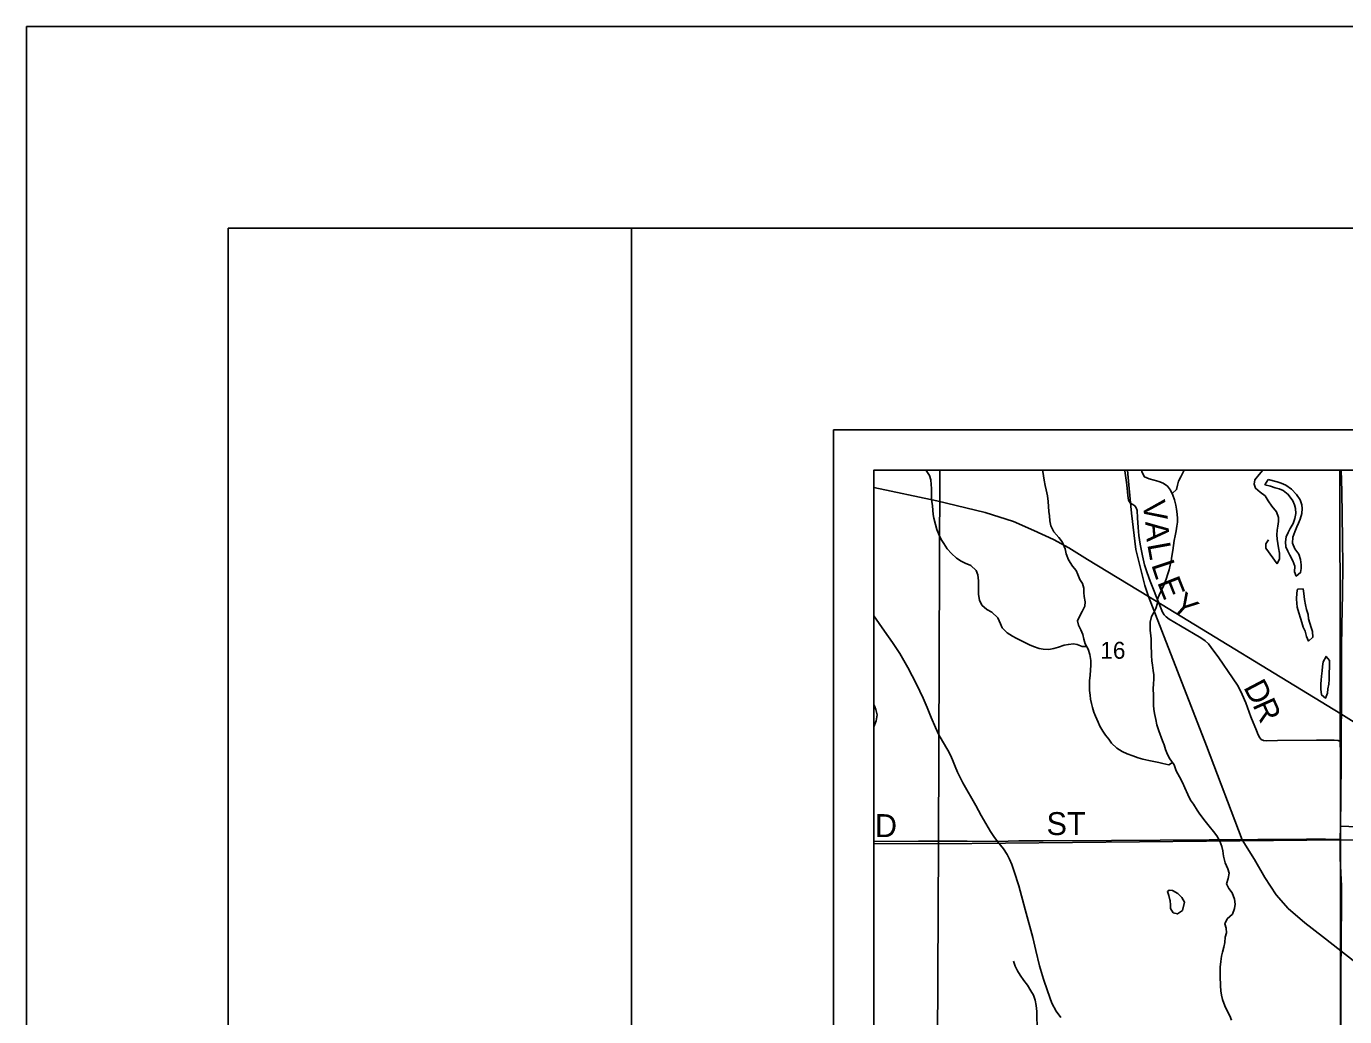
# Model space of a CAD drawing. Extents: x 0 to 34, y 0 to 22.
# Drawn here: x 0 to 3.267, y 19.546 to 22 of the extents above; entities that cross this region are included whole.
import ezdxf

# ---------------------------------------------------------------- set-up
doc = ezdxf.new("R2010")
doc.units = 0
for name, color, linetype in [('Default', 7, 'Continuous'), ('SH_Border', 7, 'Continuous'), ('SH_Cut_Line', 7, 'Continuous'), ('SH_Data', 7, 'Continuous')]:
    doc.layers.add(name, color=color, linetype=linetype)

msp = doc.modelspace()

# ---------------------------------------------------------------- linework, layer by layer
at = {"layer": 'Default'}
msp.add_line((3.2569, 20.0177), (3.2565, 19.9852), dxfattribs=at)
for points in [[(2.264, 20.9), (2.1, 20.9), (2.1, 19.9754), (2.2603, 19.9741)], [(3.255, 20.9), (2.264, 20.9), (2.2603, 19.9741), (3.2572, 19.9844)], [(4.26, 20.9), (3.255, 20.9), (3.2572, 19.9844), (4.2696, 19.9768)], [(2.1, 19.9754), (2.1, 18.9883), (2.2553, 18.9881), (2.2603, 19.9741)], [(2.2603, 19.9741), (3.2572, 19.9844), (3.2565, 18.9852), (2.2553, 18.9881)], [(4.2696, 19.9768), (4.2649, 18.9814), (3.2565, 18.9852), (3.2572, 19.9844)]]:
    msp.add_lwpolyline(points, close=True, dxfattribs=at)
for points in [[(6.2315, 20.9), (2.1, 20.9), (2.1, 17.0156)], [(2.6277, 20.4635), (2.6166, 20.463), (2.6044, 20.4685), (2.5949, 20.4695), (2.5824, 20.4686), (2.5718, 20.4662), (2.5579, 20.4618), (2.5465, 20.4582), (2.5344, 20.4561), (2.5204, 20.4563), (2.5097, 20.4581), (2.496, 20.4636), (2.4865, 20.4672), (2.4766, 20.472), (2.4628, 20.4791), (2.4533, 20.4842), (2.4437, 20.489), (2.4307, 20.4972), (2.418, 20.5096), (2.4141, 20.5198), (2.4074, 20.5341), (2.3932, 20.548), (2.3806, 20.555), (2.3683, 20.5658), (2.3621, 20.5779), (2.36, 20.5923), (2.3595, 20.6258), (2.3582, 20.6405), (2.3542, 20.6515), (2.3404, 20.6639), (2.327, 20.6694), (2.3171, 20.6745), (2.3052, 20.682), (2.2926, 20.6936), (2.2822, 20.7056), (2.2736, 20.7184), (2.2674, 20.7282), (2.2624, 20.7391), (2.2568, 20.7535), (2.2533, 20.7652), (2.2493, 20.7811), (2.2476, 20.7906), (2.2463, 20.8012), (2.2454, 20.8122), (2.2441, 20.8228), (2.2436, 20.8331), (2.2431, 20.8437), (2.2433, 20.8551), (2.2428, 20.8646), (2.2419, 20.8764), (2.2387, 20.8869), (2.2313, 20.8971), (2.2293, 20.9)], [(2.8403, 20.1758), (2.8315, 20.1701), (2.8167, 20.1733), (2.8064, 20.1758), (2.7939, 20.1787), (2.7817, 20.1808), (2.7669, 20.184), (2.7551, 20.1876), (2.7421, 20.192), (2.728, 20.1971), (2.7154, 20.2027), (2.7028, 20.2112), (2.6893, 20.2236), (2.6824, 20.2333), (2.6747, 20.2435), (2.6677, 20.2533), (2.6607, 20.2657), (2.656, 20.2759), (2.6494, 20.2906), (2.6458, 20.3008), (2.6426, 20.3118), (2.6394, 20.3224), (2.6374, 20.3326), (2.6361, 20.3425), (2.6352, 20.3539), (2.6347, 20.3649), (2.6352, 20.3786), (2.6366, 20.3919), (2.6375, 20.4048), (2.6381, 20.4173), (2.6383, 20.4284), (2.6359, 20.4432), (2.6319, 20.4564), (2.6241, 20.4696), (2.6205, 20.4817), (2.6185, 20.4934), (2.613, 20.5044), (2.6079, 20.5161), (2.6051, 20.5267), (2.6095, 20.5362), (2.6169, 20.55), (2.6232, 20.5634), (2.6245, 20.5737), (2.6217, 20.5873), (2.6212, 20.5972), (2.6207, 20.6078), (2.6171, 20.6196), (2.6105, 20.6293), (2.6058, 20.6414), (2.6019, 20.6513), (2.5926, 20.6625), (2.5829, 20.678), (2.577, 20.6927), (2.5742, 20.7056), (2.5675, 20.7229), (2.559, 20.7331), (2.5463, 20.7477), (2.5392, 20.7624), (2.5368, 20.7749), (2.5355, 20.7867), (2.5342, 20.7981), (2.5333, 20.8106), (2.5323, 20.8224), (2.531, 20.8368), (2.5278, 20.8519), (2.525, 20.8622), (2.5221, 20.8758), (2.5205, 20.8864), (2.5195, 20.897), (2.5193, 20.9)], [(2.7225, 20.9), (2.7228, 20.8988), (2.727, 20.8637), (2.7297, 20.8372), (2.7304, 20.8313), (2.7315, 20.8258), (2.7328, 20.8223), (2.7362, 20.8184), (2.742, 20.8153), (2.7472, 20.8119), (2.7505, 20.8071), (2.7526, 20.8006), (2.754, 20.7823), (2.7555, 20.7585), (2.7574, 20.7381), (2.7604, 20.7166), (2.7658, 20.6878), (2.7714, 20.666), (2.7775, 20.6461), (2.785, 20.6255), (2.8088, 20.5649), (2.8155, 20.5481), (2.8197, 20.5415), (2.8249, 20.5364), (2.8324, 20.531), (2.8604, 20.5149), (2.9104, 20.4851), (2.9217, 20.477), (2.9296, 20.4698), (2.9367, 20.4611), (2.9556, 20.4348), (2.9893, 20.3856), (3.0032, 20.3647), (3.0136, 20.3447), (3.022, 20.3233), (3.0348, 20.2893), (3.0488, 20.2548), (3.053, 20.244), (3.0567, 20.2368), (3.0606, 20.2327), (3.0662, 20.2305), (3.0745, 20.2295), (3.1008, 20.2303), (3.1972, 20.2314), (3.2413, 20.2313), (3.2508, 20.2301), (3.2588, 20.2269)], [(2.781, 20.587), (2.7716, 20.6142), (2.7495, 20.7034), (2.7391, 20.7939), (2.7332, 20.8547), (2.7289, 20.9)], [(2.9741, 19.8754), (2.9788, 19.8884), (2.9809, 19.9014), (2.9777, 19.912), (2.9711, 19.9274), (2.9667, 19.9433), (2.9654, 19.9566), (2.9629, 19.9676), (2.9582, 19.9808), (2.9508, 19.994), (2.9423, 20.0045), (2.9315, 20.0177), (2.9215, 20.0305), (2.9087, 20.0477), (2.9021, 20.0579), (2.8928, 20.0722), (2.8851, 20.0827), (2.8785, 20.0967), (2.8714, 20.1133), (2.8651, 20.1262), (2.8581, 20.1401), (2.85, 20.1552), (2.8444, 20.1699), (2.834, 20.185), (2.8285, 20.1955), (2.823, 20.2084), (2.8195, 20.2197), (2.8155, 20.2295), (2.8069, 20.2545), (2.8021, 20.2689), (2.7989, 20.2825), (2.796, 20.2973), (2.7947, 20.3079), (2.7938, 20.3174), (2.7935, 20.3424), (2.7929, 20.358), (2.7935, 20.3706), (2.7941, 20.3827), (2.7939, 20.393), (2.793, 20.4036), (2.7913, 20.4173), (2.7897, 20.4275), (2.7883, 20.4412), (2.7879, 20.4696), (2.7874, 20.4814), (2.7865, 20.4909), (2.7856, 20.5027), (2.785, 20.5133), (2.7853, 20.5239), (2.7881, 20.5373), (2.794, 20.5476), (2.7996, 20.5576), (2.8036, 20.5709), (2.8031, 20.5808), (2.8079, 20.5907), (2.8134, 20.603), (2.8193, 20.6156), (2.8251, 20.6305), (2.8291, 20.6431), (2.832, 20.653), (2.8349, 20.6652), (2.8374, 20.6751), (2.8391, 20.6873), (2.8412, 20.7014), (2.8429, 20.7136), (2.845, 20.7258), (2.8475, 20.7372), (2.85, 20.7498), (2.8517, 20.7616), (2.8527, 20.7711), (2.8526, 20.7806), (2.8521, 20.7912), (2.8508, 20.8037), (2.8491, 20.8136), (2.8459, 20.8268), (2.8416, 20.8386), (2.8357, 20.8503), (2.828, 20.8604), (2.8176, 20.8679), (2.807, 20.8723), (2.7948, 20.8755), (2.783, 20.8791), (2.7708, 20.8839), (2.7645, 20.896), (2.764, 20.9)], [(2.8395, 20.8428), (2.8505, 20.852), (2.853, 20.863), (2.8555, 20.873), (2.8614, 20.8841), (2.8691, 20.9)], [(3.0999, 20.6682), (3.1058, 20.6805), (3.1056, 20.6942), (3.1035, 20.7074), (3.1019, 20.7188), (3.1002, 20.7294), (3.0993, 20.74), (3.1003, 20.7518), (3.1016, 20.7614), (3.103, 20.7728), (3.1036, 20.783), (3.0985, 20.7974), (3.0865, 20.8113), (3.0773, 20.8245), (3.0699, 20.8369), (3.058, 20.8458), (3.0461, 20.8555), (3.0426, 20.8654), (3.0443, 20.876), (3.0555, 20.8899), (3.0646, 20.9)], [(3.0773, 20.8773), (3.0695, 20.8642), (3.0832, 20.8603), (3.0954, 20.8566), (3.1049, 20.8537), (3.1148, 20.8497), (3.1275, 20.84), (3.1387, 20.8246), (3.1426, 20.8147), (3.1454, 20.8049), (3.146, 20.7928), (3.1439, 20.7806), (3.1395, 20.768), (3.1321, 20.7553), (3.1269, 20.7458), (3.1225, 20.7351), (3.1208, 20.7229), (3.1217, 20.71), (3.126, 20.6998), (3.1315, 20.6896), (3.1389, 20.6753), (3.144, 20.6624), (3.1427, 20.6483), (3.1474, 20.6378), (3.1579, 20.6463), (3.1592, 20.6566), (3.1591, 20.666), (3.1582, 20.679), (3.1534, 20.6922), (3.1441, 20.7057), (3.1383, 20.7193), (3.1388, 20.7341), (3.1436, 20.7471), (3.1487, 20.7597), (3.1527, 20.7693), (3.1572, 20.7789), (3.1615, 20.793), (3.1621, 20.8051), (3.1612, 20.8146), (3.1572, 20.8271), (3.1476, 20.8403), (3.1353, 20.853), (3.1215, 20.8631), (3.1096, 20.8682), (3.0997, 20.8715)], [(3.0997, 20.8715), (3.0773, 20.8773)], [(3.2588, 20.9), (3.2605, 20.8484), (3.2622, 20.7283), (3.2625, 20.6644), (3.2621, 20.5948), (3.2603, 20.5145), (3.2594, 20.4608), (3.2595, 20.339), (3.2588, 20.2269), (3.2585, 20.1792), (3.2576, 20.0891), (3.2569, 20.0177)], [(2.1, 20.8575), (2.2567, 20.8241), (2.3763, 20.795), (2.4461, 20.7727), (2.4969, 20.7508), (2.5458, 20.7283), (2.5839, 20.7079), (2.6302, 20.6791), (2.781, 20.587)], [(3.0786, 20.728), (3.072, 20.7177), (3.072, 20.7071), (3.0999, 20.6682)], [(2.781, 20.587), (3.2581, 20.2961), (3.5691, 20.1012), (3.6469, 20.0395), (3.6858, 20.0076), (4.1277, 19.5854), (4.2882, 19.4298), (4.7959, 18.9483), (4.8867, 18.8627), (4.9397, 18.8161), (4.9914, 18.7791), (5.0638, 18.7415), (5.1188, 18.7201), (5.1744, 18.7071), (5.2205, 18.7028), (5.2754, 18.7016), (5.3374, 18.6952), (5.4602, 18.6836), (5.597, 18.6827), (5.698, 18.6656), (5.9841, 18.6456), (6.1617, 18.6371), (6.2768, 18.6314)], [(3.3531, 19.6346), (3.2123, 19.745), (3.1688, 19.7783), (3.1275, 19.8144), (3.0976, 19.848), (3.0692, 19.8907), (3.0438, 19.9355), (3.013, 19.9839), (2.925, 20.2172), (2.781, 20.587)], [(3.1501, 20.6055), (3.1487, 20.596), (3.1478, 20.5804), (3.1483, 20.5709), (3.1496, 20.5607), (3.1539, 20.5471), (3.1579, 20.5331), (3.1611, 20.5225), (3.1647, 20.5115), (3.169, 20.5009), (3.173, 20.4884), (3.1777, 20.4767), (3.1885, 20.4864), (3.1872, 20.5004), (3.1844, 20.5106), (3.1812, 20.5212), (3.178, 20.5322), (3.1764, 20.5428), (3.1728, 20.5553), (3.1704, 20.5663), (3.1675, 20.5799), (3.1662, 20.5943), (3.1641, 20.6061)], [(3.1641, 20.6061), (3.1501, 20.6055)], [(2.5639, 19.5437), (2.5525, 19.5592), (2.5419, 19.5791), (2.5308, 19.6096), (2.5208, 19.6393), (2.5112, 19.6723), (2.502, 19.7101), (2.494, 19.7425), (2.4757, 19.8119), (2.4594, 19.8702), (2.4481, 19.906), (2.4423, 19.9234), (2.4369, 19.9365), (2.4305, 19.9482), (2.4213, 19.962), (2.4072, 19.9803), (2.3981, 19.9925), (2.3893, 20.005), (2.3777, 20.025), (2.3667, 20.0441), (2.3532, 20.0689), (2.3211, 20.1258), (2.314, 20.1383), (2.3076, 20.1515), (2.3016, 20.1663), (2.2953, 20.1825), (2.2903, 20.1941), (2.2836, 20.2065), (2.2703, 20.2289), (2.2617, 20.2441), (2.2531, 20.2622), (2.2427, 20.2872), (2.2326, 20.3119), (2.2224, 20.3352), (2.2058, 20.37), (2.1847, 20.4114), (2.165, 20.446), (2.1466, 20.4733), (2.127, 20.5013), (2.1, 20.539)], [(3.2295, 20.4288), (3.2211, 20.4386), (3.2137, 20.4252), (3.2127, 20.4138), (3.2117, 20.4031), (3.21, 20.3898), (3.209, 20.3799), (3.208, 20.3704), (3.2078, 20.3575), (3.2099, 20.3435), (3.2198, 20.3356), (3.225, 20.3475), (3.2256, 20.3581), (3.2281, 20.3699), (3.229, 20.3817)], [(3.229, 20.3817), (3.2295, 20.4288)], [(2.1, 20.3209), (2.101, 20.3181), (2.1053, 20.3075), (2.1089, 20.2939), (2.1065, 20.2794), (2.1002, 20.2645), (2.1, 20.2636)], [(3.2569, 20.0177), (3.2775, 20.0173), (3.2931, 20.0164), (3.3052, 20.015), (3.3163, 20.0119), (3.3262, 20.0079), (3.3676, 19.9898), (3.3789, 19.9859), (3.3898, 19.984), (3.4012, 19.9833), (3.4305, 19.9832), (3.5109, 19.9825), (3.5872, 19.9809), (3.6508, 19.9809), (3.6635, 19.9808), (3.6743, 19.9791), (3.6825, 19.976), (3.6893, 19.9715), (3.7028, 19.9589), (3.7418, 19.9219), (3.7782, 19.8872), (3.7949, 19.8708)], [(2.1, 19.9802), (2.2112, 19.9805), (2.3315, 19.9809), (2.4072, 19.9803), (2.46, 19.9814), (2.5199, 19.9814), (2.6893, 19.9829), (3.1726, 19.9858), (3.2198, 19.9855), (3.2565, 19.9852)], [(3.2565, 19.9852), (3.2557, 19.9639), (3.2561, 19.9392), (3.2581, 19.9016), (3.2594, 19.8699), (3.2596, 19.8254), (3.2589, 19.7384), (3.2581, 19.6526), (3.258, 19.5305), (3.2588, 19.4869), (3.2597, 19.4497), (3.2597, 19.3639), (3.2575, 19.2725), (3.2561, 19.1717), (3.2558, 19.0924), (3.2548, 18.8963), (3.2559, 18.8401), (3.2557, 18.8052)], [(2.9871, 19.5371), (2.9824, 19.5484), (2.9766, 19.5586), (2.9703, 19.5726), (2.9644, 19.5888), (2.9624, 19.5991), (2.9603, 19.6104), (2.9594, 19.6226), (2.9591, 19.6461), (2.9585, 19.6568), (2.9584, 19.6685), (2.9601, 19.683), (2.9618, 19.6956), (2.9643, 19.7059), (2.9679, 19.7184), (2.9704, 19.7299), (2.9714, 19.7432), (2.9742, 19.7539), (2.9733, 19.7656), (2.9701, 19.7762), (2.9764, 19.7881), (2.9895, 19.8001), (2.9946, 19.8138), (2.9956, 19.8245), (2.9943, 19.8374), (2.9888, 19.8525), (2.9799, 19.8634), (2.9741, 19.8754)], [(2.8358, 19.8138), (2.8423, 19.8033), (2.8526, 19.8004), (2.865, 19.8093), (2.87, 19.8295), (2.8638, 19.8412), (2.8534, 19.8513), (2.8408, 19.8587), (2.8325, 19.8594), (2.828, 19.8559), (2.8315, 19.846)], [(2.8315, 19.846), (2.8339, 19.8359), (2.8346, 19.8335), (2.8355, 19.8219), (2.8358, 19.8138)], [(2.505, 19.5196), (2.5046, 19.5477), (2.5041, 19.5591), (2.5024, 19.5735), (2.4999, 19.5871), (2.4963, 19.5989), (2.4893, 19.6102), (2.4808, 19.6237), (2.4723, 19.6354), (2.463, 19.6489), (2.456, 19.6598), (2.4506, 19.6715), (2.4462, 19.6833)]]:
    msp.add_lwpolyline(points, dxfattribs=at)
at = {"layer": 'SH_Border'}
for points in [[(0.5, 21.5), (1.5, 21.5), (1.5, 0.5), (0.5, 0.5)], [(1.5, 21.5), (33.5, 21.5), (33.5, 0.5), (1.5, 0.5)]]:
    msp.add_lwpolyline(points, close=True, dxfattribs=at)
at = {"layer": 'SH_Cut_Line'}
msp.add_lwpolyline([(0, 0), (34, 0), (34, 22), (0, 22)], close=True, dxfattribs=at)
msp.add_lwpolyline([(6.2315, 20.9), (2.1, 20.9), (2.1, 17.0156)], dxfattribs=at)
at = {"layer": 'SH_Data'}
for p, q in [((2, 21), (9, 21)), ((2, 21), (2, 14)), ((2.1, 20.9), (2.1, 14.1)), ((2.1, 20.9), (8.9, 20.9))]:
    msp.add_line(p, q, dxfattribs=at)

# ---------------------------------------------------------------- texts
at = {"layer": 'Default'}
for s, height, rotation, p in [('V', 0.0568, 278.6886, (2.7655, 20.8208)), ('A', 0.0568, 274.6898, (2.7729, 20.7724)), ('L', 0.0568, 280.2416, (2.7778, 20.7166)), ('L', 0.0568, 288.2762, (2.7875, 20.6663)), ('E', 0.0568, 291.6263, (2.8021, 20.6226)), ('Y', 0.0568, 318.6363, (2.8344, 20.5594)), ('16', 0.04186, 0, (2.6617, 20.4329)), ('D', 0.0568, 297.7837, (3.0152, 20.3623)), ('R', 0.0568, 294.1575, (3.0381, 20.3189)), ('D', 0.0568, 0, (2.103, 19.991)), ('ST', 0.05682, 0, (2.5283, 19.996))]:
    msp.add_text(s, height=height, rotation=rotation, dxfattribs=at).set_placement(p)

doc.saveas('drawing.dxf')
